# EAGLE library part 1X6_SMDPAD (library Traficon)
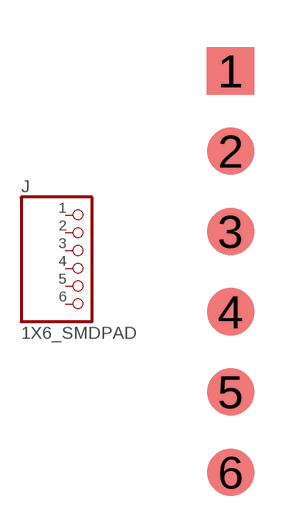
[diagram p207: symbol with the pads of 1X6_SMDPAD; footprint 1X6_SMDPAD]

Designator prefix J

## 1X6_SMDPAD  [1X6_SMDPAD]
1  1  pas
2  2  pas
3  3  pas
4  4  pas
5  5  pas
6  6  pas

## Footprint 1X6_SMDPAD (pad centres in mm)
smd 1.5 x 1.5: 1 0,7.62; 2 0,5.08; 3 0,2.54; 4 0,0; 5 0,-2.54; 6 0,-5.08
